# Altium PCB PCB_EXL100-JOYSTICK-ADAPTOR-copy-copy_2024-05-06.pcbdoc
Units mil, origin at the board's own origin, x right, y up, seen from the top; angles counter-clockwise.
Board outline 14061.15 x 6354.32 mil, 2 copper layers (Top Layer, Bottom Layer); 102 components, 39 nets, 293 pads, 23 vias.
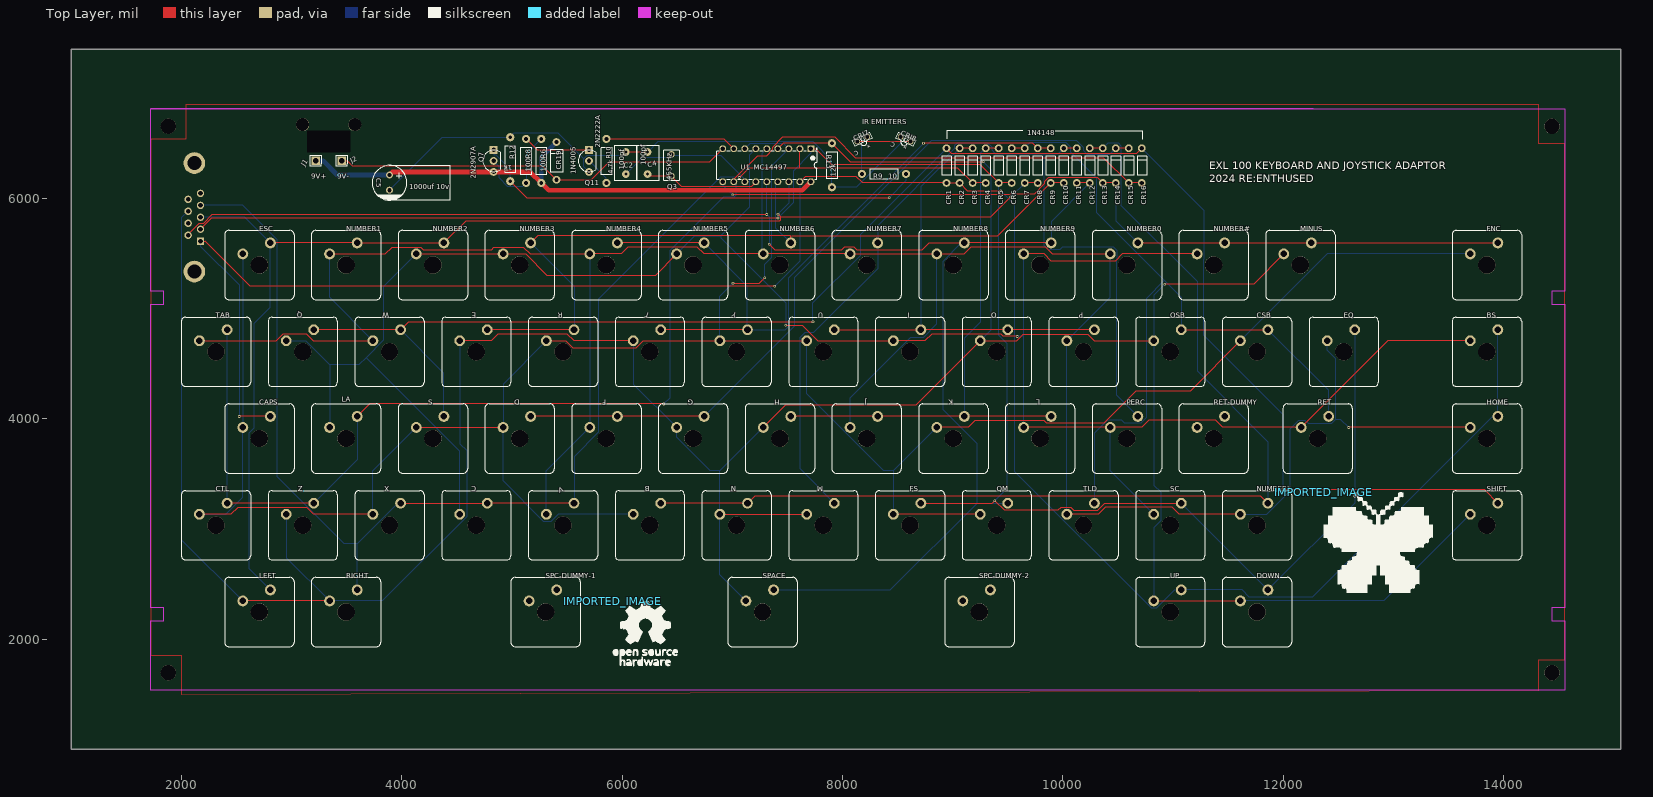
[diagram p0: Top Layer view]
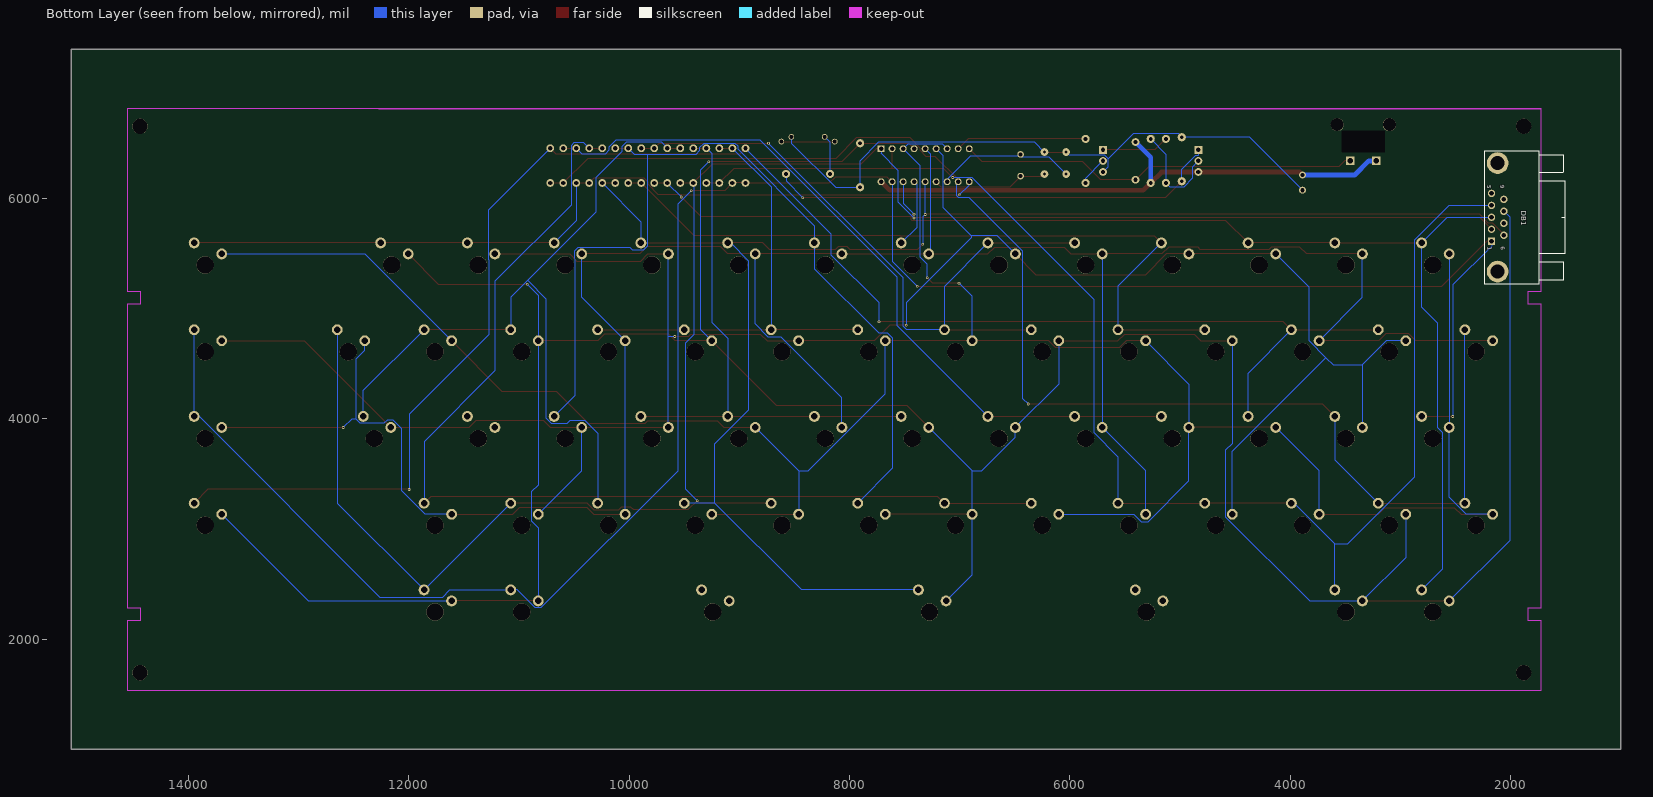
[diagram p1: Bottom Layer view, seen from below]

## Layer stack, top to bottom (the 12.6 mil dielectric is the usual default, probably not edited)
Top Layer: signal copper (thickness not stored)
Dielectric: dielectric 12.6, FR-4, Dk 4.8
Bottom Layer: signal copper (thickness not stored)

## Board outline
15061.15,1000 1000,1000 1000,7354.32 15061.15,7354.32
cut-out: 3138.86,6618.1 3532.58,6618.1 3532.56,6421.25 3138.86,6421.25

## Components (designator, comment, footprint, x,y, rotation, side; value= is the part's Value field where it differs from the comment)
B "Outemu Switch" "OUTEMU MX SWITCH FULL BOX" 6249.09,3035.43 r0 top
BS "Outemu Switch" "OUTEMU MX SWITCH FULL BOX" 13847.51,4610.23 r0 top
C "Outemu Switch" "OUTEMU MX SWITCH FULL BOX" 4674.29,3035.43 r0 top
C2 "100pf" RAD-0.2 6032.55,6322.82 r90 top
C4 "100pf" RAD-0.2 6229.4,6322.82 r90 top
C5 "1000uf 10v" CAP-D8.0-F3.5 3886.89,6145.66 r270 top
CAPS "Outemu Switch" "OUTEMU MX SWITCH FULL BOX" 2705.79,3822.83 r0 top
CR1 "1N4148" DO-35_BD2.0-L4.0-P8.00-D0.5-FD 8942.83,6299.99 r90 top
CR2 "1N4148" DO-35_BD2.0-L4.0-P8.00-D0.5-FD 9061.83,6299.99 r90 top
CR3 "1N4148" DO-35_BD2.0-L4.0-P8.00-D0.5-FD 9179.93,6299.99 r90 top
CR4 "1N4148" DO-35_BD2.0-L4.0-P8.00-D0.5-FD 9298.03,6299.99 r90 top
CR5 "1N4148" DO-35_BD2.0-L4.0-P8.00-D0.5-FD 9416.13,6299.99 r90 top
CR6 "1N4148" DO-35_BD2.0-L4.0-P8.00-D0.5-FD 9534.23,6299.99 r90 top
CR7 "1N4148" DO-35_BD2.0-L4.0-P8.00-D0.5-FD 9652.33,6299.99 r90 top
CR8 "1N4148" DO-35_BD2.0-L4.0-P8.00-D0.5-FD 9770.43,6299.99 r90 top
CR9 "1N4148" DO-35_BD2.0-L4.0-P8.00-D0.5-FD 9888.53,6299.99 r90 top
CR10 "1N4148" DO-35_BD2.0-L4.0-P8.00-D0.5-FD 10006.73,6299.99 r90 top
CR11 "1N4148" DO-35_BD2.0-L4.0-P8.00-D0.5-FD 10124.83,6299.99 r90 top
CR12 "1N4148" DO-35_BD2.0-L4.0-P8.00-D0.5-FD 10242.93,6299.99 r90 top
CR13 "1N4148" DO-35_BD2.0-L4.0-P8.00-D0.5-FD 10361.03,6299.99 r90 top
CR14 "1N4148" DO-35_BD2.0-L4.0-P8.00-D0.5-FD 10479.13,6299.99 r90 top
CR15 "1N4148" DO-35_BD2.0-L4.0-P8.00-D0.5-FD 10597.23,6299.99 r90 top
CR16 "1N4148" DO-35_BD2.0-L4.0-P8.00-D0.5-FD 10715.33,6299.99 r90 top
CR19 "1N4005" DO-41_BD2.4-L4.7-P8.70-D0.9-RD 5402.59,6342.47 r270 top
CRI7 "XC8810" LTE-302 8178.22,6539.36 r25 top
CRI8 "XC8810" LTE-302 8571.92,6539.36 r335 top
CSB "Outemu Switch" "OUTEMU MX SWITCH FULL BOX" 11760.89,4610.23 r0 top
CTL "Outemu Switch" "OUTEMU MX SWITCH FULL BOX" 2312.09,3035.43 r0 top
D "Outemu Switch" "OUTEMU MX SWITCH FULL BOX" 5067.99,3822.83 r0 top
DB1 "DB9_Male" DSUB-TH_DMR-9P 2115.24,5830.7 r0 bottom
DOWN "Outemu Switch" "OUTEMU MX SWITCH FULL BOX" 11760.89,2248.03 r0 top
E "Outemu Switch" "OUTEMU MX SWITCH FULL BOX" 4674.29,4610.23 r0 top
EQ "Outemu Switch" "OUTEMU MX SWITCH FULL BOX" 12548.29,4610.23 r0 top
ESC "Outemu Switch" "OUTEMU MX SWITCH FULL BOX" 2705.79,5397.63 r0 top
F "Outemu Switch" "OUTEMU MX SWITCH FULL BOX" 5855.39,3822.83 r0 top
FNC "Outemu Switch" "OUTEMU MX SWITCH FULL BOX" 13847.51,5397.63 r0 top
FS "Outemu Switch" "OUTEMU MX SWITCH FULL BOX" 8611.29,3035.43 r0 top
G "Outemu Switch" "OUTEMU MX SWITCH FULL BOX" 6642.79,3822.83 r0 top
H "Outemu Switch" "OUTEMU MX SWITCH FULL BOX" 7430.19,3822.83 r0 top
HOME "Outemu Switch" "OUTEMU MX SWITCH FULL BOX" 13847.51,3822.83 r0 top
I "Outemu Switch" "OUTEMU MX SWITCH FULL BOX" 8611.29,4610.23 r0 top
IMPORTED_IMAGE "IMPORTED_IMAGE" IMPORTED_IMAGE 5914.64,2346.46 r0 top
IMPORTED_IMAGE "IMPORTED_IMAGE" IMPORTED_IMAGE 12368.32,3332.87 r0 top
J "Outemu Switch" "OUTEMU MX SWITCH FULL BOX" 8217.59,3822.83 r0 top
J1 "9V+" HDR-M-2.54_1X1 3217.6,6342.51 r0 top
J2 "9V-" HDR-M-2.54_1X1 3453.82,6342.51 r0 top
K "Outemu Switch" "OUTEMU MX SWITCH FULL BOX" 9004.99,3822.83 r0 top
L "Outemu Switch" "OUTEMU MX SWITCH FULL BOX" 9792.39,3822.83 r0 top
LA "Outemu Switch" "OUTEMU MX SWITCH FULL BOX" 3493.19,3822.83 r0 top
LEFT "Outemu Switch" "OUTEMU MX SWITCH FULL BOX" 2705.79,2248.03 r0 top
M "Outemu Switch" "OUTEMU MX SWITCH FULL BOX" 7823.89,3035.43 r0 top
MINUS "Outemu Switch" "OUTEMU MX SWITCH FULL BOX" 12154.59,5397.63 r0 top
N "Outemu Switch" "OUTEMU MX SWITCH FULL BOX" 7036.49,3035.43 r0 top
NUMBER0 "Outemu Switch" "OUTEMU MX SWITCH FULL BOX" 10579.79,5397.63 r0 top
NUMBER1 "Outemu Switch" "OUTEMU MX SWITCH FULL BOX" 3493.19,5397.63 r0 top
NUMBER2 "Outemu Switch" "OUTEMU MX SWITCH FULL BOX" 4280.59,5397.63 r0 top
NUMBER3 "Outemu Switch" "OUTEMU MX SWITCH FULL BOX" 5067.99,5397.63 r0 top
NUMBER4 "Outemu Switch" "OUTEMU MX SWITCH FULL BOX" 5855.39,5397.63 r0 top
NUMBER5 "Outemu Switch" "OUTEMU MX SWITCH FULL BOX" 6642.79,5397.63 r0 top
NUMBER6 "Outemu Switch" "OUTEMU MX SWITCH FULL BOX" 7430.19,5397.63 r0 top
NUMBER7 "Outemu Switch" "OUTEMU MX SWITCH FULL BOX" 8217.59,5397.63 r0 top
NUMBER8 "Outemu Switch" "OUTEMU MX SWITCH FULL BOX" 9004.99,5397.63 r0 top
NUMBER9 "Outemu Switch" "OUTEMU MX SWITCH FULL BOX" 9792.39,5397.63 r0 top
NUMBER# "Outemu Switch" "OUTEMU MX SWITCH FULL BOX" 11367.19,5397.63 r0 top
NUMBER* "Outemu Switch" "OUTEMU MX SWITCH FULL BOX" 11760.89,3035.43 r0 top
O "Outemu Switch" "OUTEMU MX SWITCH FULL BOX" 9398.69,4610.23 r0 top
OSB "Outemu Switch" "OUTEMU MX SWITCH FULL BOX" 10973.49,4610.23 r0 top
P "Outemu Switch" "OUTEMU MX SWITCH FULL BOX" 10186.09,4610.23 r0 top
PERC "Outemu Switch" "OUTEMU MX SWITCH FULL BOX" 10579.79,3822.83 r0 top
Q "Outemu Switch" "OUTEMU MX SWITCH FULL BOX" 3099.49,4610.23 r0 top
Q3 "455KHz" FILTER-TH_2P-L7.0-W3.5-P5.00 6445.94,6303.14 r90 top
Q7 "2N2907A" TO-92-3_L4.8-W3.7-P2.54-R 4831.77,6342.51 r90 top
Q11 "2N2222A" TO-92-3_L4.8-W3.7-P2.54-R 5697.91,6342.51 r90 top
QM "Outemu Switch" "OUTEMU MX SWITCH FULL BOX" 9398.69,3035.43 r0 top
R "Outemu Switch" "OUTEMU MX SWITCH FULL BOX" 5461.69,4610.23 r0 top
R6 "100" R_AXIAL-0.4 5264.84,6342.51 r90 top
R8 "100" R_AXIAL-0.4 5127.04,6342.51 r90 top
R9 "10" R_AXIAL-0.4 8375.07,6224.4 r180 top
R10 "4.7k" R_AXIAL-0.4 5855.39,6342.51 r90 top
R12 "1k" R_AXIAL-0.4 4982.74,6357.53 r90 top
R13 "12k" R_AXIAL-0.4 7902.63,6303.14 r270 top
RET "Outemu Switch" "OUTEMU MX SWITCH FULL BOX" 12312.07,3822.83 r0 top
RET-DUMMY "K2-3.6×6.1" "OUTEMU MX SWITCH FULL BOX" 11367.19,3822.83 r0 top
RIGHT "Outemu Switch" "OUTEMU MX SWITCH FULL BOX" 3493.19,2248.03 r0 top
S "Outemu Switch" "OUTEMU MX SWITCH FULL BOX" 4280.59,3822.83 r0 top
SC "Outemu Switch" "OUTEMU MX SWITCH FULL BOX" 10973.49,3035.43 r0 top
SHIFT "Outemu Switch" "OUTEMU MX SWITCH FULL BOX" 13847.51,3035.43 r0 top
SPACE "Outemu Switch" "OUTEMU MX SWITCH FULL BOX" 7272.71,2248.03 r0 top
SPC-DUMMY-1 "K2-3.6×6.1" "OUTEMU MX SWITCH FULL BOX" 5304.21,2248.03 r0 top
SPC-DUMMY-2 "K2-3.6×6.1" "OUTEMU MX SWITCH FULL BOX" 9241.21,2248.03 r0 top
T "Outemu Switch" "OUTEMU MX SWITCH FULL BOX" 6249.09,4610.23 r0 top
TAB "Outemu Switch" "OUTEMU MX SWITCH FULL BOX" 2312.09,4610.23 r0 top
TLD "Outemu Switch" "OUTEMU MX SWITCH FULL BOX" 10186.09,3035.43 r0 top
U "Outemu Switch" "OUTEMU MX SWITCH FULL BOX" 7823.89,4610.23 r0 top
U1 "MC14497" DIP-18_L23.0-W6.5-P2.54-LS7.6-BL 7312.08,6303.14 r180 top
UP "Outemu Switch" "OUTEMU MX SWITCH FULL BOX" 10973.49,2248.03 r0 top
V "Outemu Switch" "OUTEMU MX SWITCH FULL BOX" 5461.69,3035.43 r0 top
W "Outemu Switch" "OUTEMU MX SWITCH FULL BOX" 3886.89,4610.23 r0 top
X "Outemu Switch" "OUTEMU MX SWITCH FULL BOX" 3886.89,3035.43 r0 top
Y "Outemu Switch" "OUTEMU MX SWITCH FULL BOX" 7036.49,4610.23 r0 top
Z "Outemu Switch" "OUTEMU MX SWITCH FULL BOX" 3099.49,3035.43 r0 top
? "" ? 11728.46,2818.87 r0 top

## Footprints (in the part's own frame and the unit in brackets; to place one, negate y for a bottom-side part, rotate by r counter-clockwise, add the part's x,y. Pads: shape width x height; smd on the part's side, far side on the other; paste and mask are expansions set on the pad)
CAP-D8.0-F3.5 [mm]
  round 1.6 hole 1 paste+0 mask+0.051: 1(-1.75,0) 2(1.75,0)
  silkscreen extent -3.96,-4 4.04,4
DIP-18_L23.0-W6.5-P2.54-LS7.6-BL [mm]
  rect 1.6x1.6 hole 1 paste+0 mask+0.051: 1(-10.16,-3.81)
  round 1.6 hole 1 paste+0 mask+0.051: 2(-7.62,-3.81) 3(-5.08,-3.81) 4(-2.54,-3.81) 5(0,-3.81) 6(2.54,-3.81) 7(5.08,-3.81) 8(7.62,-3.81) 9(10.16,-3.81) 10(10.16,3.81) 11(7.62,3.81) 12(5.08,3.81) 13(2.54,3.81) 14(0,3.81) 15(-2.54,3.81) 16(-5.08,3.81) 17(-7.62,3.81) 18(-10.16,3.81)
  silkscreen extent -11.58,-3.93 11.5,3.25
DO-35_BD2.0-L4.0-P8.00-D0.5-FD [mm]
  round 1.8 hole 1 paste+0 mask+0.051: 1(-4,0) 2(4,0)
  silkscreen extent -2.2,-1.1 2.2,1.1
DO-41_BD2.4-L4.7-P8.70-D0.9-RD [mm]
  round 1.8 hole 1 paste+0 mask+0.051: 1(-4.35,0) 2(4.35,0)
  silkscreen extent -2.6,-1.4 2.6,1.4
DSUB-TH_DMR-9P [mm]
  rect 1.7x1.7 hole 1.1 paste+0 mask+0.051: 1(1.42,5.52)
  round 1.7 hole 1.1 paste+0 mask+0.051: 2(1.42,2.76) 3(1.42,0) 4(1.42,-2.76) 5(1.42,-5.52) 6(-1.42,4.14) 7(-1.42,1.38) 8(-1.42,-1.38) 9(-1.42,-4.14)
  round 5 hole 3.25 paste+0 mask+0.051: 10(0,-12.5) 11(0,12.5)
  silkscreen extent -15.5,-15.4 3,15.4
FILTER-TH_2P-L7.0-W3.5-P5.00 [mil]
  round 60 hole 36 paste+0 mask+2: 1(-98.4,0) 2(98.4,0)
  silkscreen extent -138,-69 138,69
HDR-M-2.54_1X1 [mm]
  rect 2x2 hole 1.3 paste+0 mask+0.051: 1(0,0)
  silkscreen extent -1.27,-1.27 1.27,1.27
IMPORTED_IMAGE [mil]
  silkscreen extent 0,-591 590,0
LTE-302 [mil]
  round 51.5 hole 31.5 slot 31.7 at 0 deg paste+0 mask+4: A(50,0) C(-50,0)
  silkscreen extent -85,-60 85,30
"OUTEMU MX SWITCH FULL BOX" [mm]
  round 2.5 hole 1.5 paste+0 mask+0.102: 1(-3.81,2.54) 2(2.54,5.08)
  round 4 hole 4 unplated paste+0: ""(0,0)
  silkscreen extent -8,-8 8,8
R_AXIAL-0.4 [mil]
  round 74 hole 35.4 paste+0 mask+2: 1(-200,0) 2(200,0)
  silkscreen extent -124,-47 124,47
RAD-0.2 [mil]
  round 70 hole 28 paste+0 mask+2: 1(100,0) 2(-100,0)
  silkscreen extent -160,-100 160,100
TO-92-3_L4.8-W3.7-P2.54-R [mm]
  rect 1.8x1.8 hole 1 paste+0 mask+0.051: 1(2.54,0)
  round 1.8 hole 1 paste+0 mask+0.051: 2(0,0) 3(-2.54,0)
  silkscreen extent -2.48,-1.5 2.48,2.48
? [mil]

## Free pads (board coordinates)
  round 137.8 hole 137.8 unplated paste+0: ""(1879.02,1696.85) ""(1879.02,6657.47) ""(14438.05,1696.85) ""(14438.05,6657.47)
  round 118.11 hole 118.11 unplated paste+0: ""(3099.49,6671.25) ""(3571.93,6671.25)

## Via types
v1: diameter 24.02, hole 12.01, Top Layer to Bottom Layer, tented both sides, 23 vias

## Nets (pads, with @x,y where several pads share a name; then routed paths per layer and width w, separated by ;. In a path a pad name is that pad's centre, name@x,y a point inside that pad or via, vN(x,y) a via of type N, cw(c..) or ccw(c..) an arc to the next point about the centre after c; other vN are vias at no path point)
+9V: C5.1 CR19.1 J1.1 Q7.3 R6.1 U1.18 | length 5088.9
  Top Layer w43.31: C5.1 3914.01,6241.67 Q7.3@4831.77,6241.67 ; Q7.3 Q7.3@4831.77,6241.67 ; U1.18 7634.43,6075.48 5331.86,6075.48 R6.1 5165.68,6241.67 Q7.3@4831.77,6241.67
  Bottom Layer w43.31: J1.1 3286.51,6342.51 3414.47,6214.55 C5.1 ; R6.1 5264.84,6375.98 CR19.1
CONTROLGND: DB1.8 DOWN.1 E.1 G.1 H.1 LEFT.1 M.1 MINUS.1 N.1 O.1 OSB.1 R13.1 RIGHT.1 SHIFT.1 SPACE.1 T.1 U1.4 UP.1 Z.1 | length 29451.4
  Top Layer w10: LEFT.1 RIGHT.1 ; E.1 4809.45,4710.23 4870.6,4771.37 5500.55,4771.37 5561.69,4710.23 T.1 ; N.1 M.1 ; H.1 7481.14,4123.78 8662.24,4123.78 O.1 9579.31,4710.23 9639.94,4770.87 10225.44,4770.87 10286.08,4710.23 OSB.1 ; U1.4 7462.09,6503.14 R13.1 8069.64,6336.12 v1(9275.17,6336.12) ; UP.1 DOWN.1 ; v1(10922.75,5222.69) 11729.6,5222.69 MINUS.1
  Bottom Layer w10: DB1.8 2003.21,5828.91 2003.21,2900.6 LEFT.1 ; Z.1 2949.49,2741.73 RIGHT.1 3823.18,2348.03 4586.99,3111.84 4586.99,3714.57 4524.28,3777.28 E.1 ; T.1 6099.09,4316.53 G.1 6492.78,3836.46 6800.11,3529.13 6886.48,3529.13 ; SPACE.1 6886.48,2584.25 N.1 6886.48,3529.13 ; H.1 6886.48,3529.13 ; O.1 9347.91,4809.45 9347.91,6263.39 v1(9275.17,6336.12) ; UP.1 10823.49,3014.96 10886.2,3077.68 10886.2,3337.48 10823.49,3400.2 OSB.1 10823.49,5123.42 v1(10922.75,5222.69) ; DOWN.1 12910.1,2348.03 SHIFT.1
CR1_2: CR1.2 CR16.2 Q.2 S.2 SHIFT.2 W.2 | length 15037.3
  Top Layer w10: Q.2 W.2 4059.89,4883.23 v1(7730.47,4883.23) ; CR1.2 8992.65,6407.65 10665.5,6407.65 CR16.2 ; v1(11996.5,3360.38) 13822.6,3360.38 SHIFT.2
  Bottom Layer w10: W.2 4380.59,4416.53 S.2 ; v1(7730.47,4883.23) 7730.47,5054.87 8163.02,5487.43 8163.02,5677.67 CR1.2 ; CR16.2 11279.61,5893.18 11279.61,5451.71 11273.77,5445.87 11273.77,4766.67 11996.5,4043.93 v1(11996.5,3360.38)
CR2_2: CR2.2 CR3.2 I.2 O.2 P.2 U.2 | length 4272.7
  Top Layer w10: U.2 I.2 O.2 P.2 ; CR2.2 CR3.2
  Bottom Layer w10: I.2 8711.28,6106.93 CR2.2
CR4_2: CR4.2 CR5.2 H.2 J.2 K.2 L.2 | length 4994.9
  Top Layer w10: H.2 J.2 K.2 L.2 ; CR4.2 CR5.2
  Bottom Layer w10: K.2 9104.99,4731.22 9251.38,4877.61 9251.38,6410.82 CR4.2
CR7_2: CR6.2 CR7.2 CSB.2 OSB.2 RET.2 TLD.2 | length 6950
  Top Layer w10: CR6.2 CR7.2 ; OSB.2 CSB.2
  Bottom Layer w10: CR7.2 9704.84,6509.99 10027.17,6509.99 10065.78,6471.37 10065.78,6427.04 10301.99,6190.84 10301.99,5877.88 10920.9,5258.97 ; TLD.2 10286.08,3868.98 10403.61,3986.51 10534.4,3986.51 10559.75,3961.15 10705.15,3961.15 10754.68,4010.69 10754.68,5092.76 10920.9,5258.97 ; OSB.2 11073.49,5106.38 10920.9,5258.97 ; CSB.2 12412.1,4259.05 RET.2
CR9_1: CR9.1 CR10.1 E.2 NUMBER3.2 NUMBER6.2 R.2 U1.15 | length 7489.7
  Top Layer w10: E.2 R.2 ; NUMBER3.2 5233.4,5663.05 7525.02,5663.05 7530.19,5657.88 ; NUMBER6.2 7530.19,5657.88 ; CR10.1 CR9.1 9410.14,5664.12 7536.43,5664.12 7530.19,5657.88
  Bottom Layer w10: NUMBER3.2 5561.69,5203.93 R.2 ; U1.15 7389.81,6130.87 7389.81,5738 NUMBER6.2
CR9_2: CR8.2 CR9.2 NUMBER4.2 NUMBER5.2 T.2 Y.2 | length 6255.3
  Top Layer w10: NUMBER4.2 NUMBER5.2 ; T.2 Y.2 ; v1(8734.59,6503.96) 9723.93,6503.96 CR8.2 CR9.2
  Bottom Layer w10: NUMBER5.2 7136.48,5203.93 Y.2 7479.85,4810.23 7510.59,4840.97 7510.59,5279.95 v1(8734.59,6503.96)
CR10_2: CR10.2 CR11.2 M.2 NUMBER7.2 PERC.2 | length 8325.2
  Top Layer w10: CR10.2 CR11.2
  Bottom Layer w10: M.2 7608.52,3550.79 7608.52,4735.1 7654.85,4781.43 7733.44,4781.43 8317.58,5365.57 NUMBER7.2 8317.58,5755.27 9014.94,6452.63 9014.94,6478.57 9040.91,6504.53 9318.74,6504.53 9357.07,6466.2 9357.07,6438.66 9390.67,6405.05 9828.32,6405.05 ; CR10.2 9954.31,6405.05 9828.32,6405.05 ; PERC.2 10487.38,4215.24 10487.38,5450.7 10493.78,5457.11 10493.78,5526.15 10462.03,5557.9 9994.43,5557.9 9970.49,5533.95 9866.19,5533.95 9828.32,5571.83 9828.32,6405.05
CR12_2: B.2 CR12.2 CR13.2 N.2 NUMBER*.2 | length 9677.1
  Top Layer w10: B.2 N.2 7200.65,3299.59 11796.7,3299.59 NUMBER*.2 ; CR12.2 CR13.2
  Bottom Layer w10: CR13.2 10409.08,6505.53 10502.31,6505.53 10525.61,6482.22 10525.61,5940.98 11216.81,5249.79 11216.81,4438.72 11860.91,3794.64 NUMBER*.2
CR13_1: CR13.1 CR14.1 FNC.2 MINUS.2 NUMBER0.2 NUMBER#.2 U1.10 | length 7625.3
  Top Layer w10: v1(7002.01,6033.84) 9512.95,6033.84 9520.65,6041.53 9737.31,6041.53 9829.49,6133.71 9829.49,6154.42 9864.34,6189.28 10314.25,6189.28 CR13.1 CR14.1 ; NUMBER0.2 NUMBER#.2 MINUS.2 FNC.2
  Bottom Layer w10: U1.10 6912.09,6123.76 v1(7002.01,6033.84) ; CR14.1 10479.12,5798.29 NUMBER0.2
CR14_2: CR14.2 CR15.2 D.2 F.2 G.2 | length 6813.8
  Top Layer w10: D.2 F.2 G.2 ; CR14.2 CR15.2
  Bottom Layer w10: G.2 7566.8,4846.84 7566.8,5285.59 8810.47,6529.26 10118.9,6529.26 10183.89,6464.27 10183.89,6437.63 10217.16,6404.36 10426.01,6404.36 CR14.2
CR15_1: CR15.1 CR16.1 CTL.2 LA.2 TAB.2 U1.11 Z.2 | length 12561.8
  Top Layer w10: CTL.2 Z.2 ; LA.2 3706.97,4136.62 v1(6376.72,4136.62) ; U1.11 7012.09,6174.35 7223.23,6385.49 7305.99,6385.49 7362.1,6441.6 7362.1,6463.88 7453.31,6555.08 7931.82,6555.08 8119.39,6367.52 10372.22,6367.52 CR15.1 CR16.1
  Bottom Layer w10: CTL.2 TAB.2 ; Z.2 3593.18,3629.13 LA.2 ; v1(6376.72,4136.62) 6429.48,4189.39 6429.48,5526.13 6914.12,6010.77 7012.27,6010.77 7030.41,6028.92 7030.41,6134.81 U1.11
CRI7_C: CRI7.C CRI8.A | length 484.3
  Top Layer w10: CRI7.C CRI8.A
DOWN: CR5.1 CR6.1 DB1.2 DOWN.2 EQ.2 FS.2 SC.2 U1.1 | length 17207.9
  Top Layer w10: DB1.2 2273.78,5824.67 v1(7413.95,5824.67) ; U1.1 7754.56,6453.14 7894.65,6313.05 9245.58,6313.05 CR5.1 CR6.1 ; FS.2 9356.89,3235.43 v1(9380.36,3258.91) 9464.82,3174.46 9959.25,3174.46 9985.53,3200.74 10070.77,3200.74 10097.69,3173.82 10317.83,3173.82 10379.43,3235.43 SC.2
  Bottom Layer w10: v1(7413.95,5824.67) 7554.65,5965.36 7554.65,6253.22 7712.07,6410.65 U1.1 ; v1(9380.36,3258.91) 9490.27,3368.82 9490.27,4686.71 9411.74,4765.25 9411.74,6138.12 CR5.1 ; SC.2 DOWN.2 12648.31,3235.43 EQ.2
FIRE: CR11.1 CR12.1 DB1.6 NUMBER8.2 NUMBER9.2 QM.2 SPACE.2 U1.14 | length 14384.7
  Top Layer w10: DB1.6 2059.34,5675.71 2159.99,5776.37 2199.28,5776.37 2279.51,5856.59 v1(7312.09,5856.59) ; v1(7333.81,5587.51) 7384.81,5536.51 7990.6,5536.51 8017.03,5562.94 8102.27,5562.94 8130.34,5534.88 8724.18,5534.88 8786.93,5597.63 NUMBER8.2 NUMBER9.2 ; CR11.1 CR12.1
  Bottom Layer w10: U1.14 v1(7312.09,5856.59) 7333.81,5834.86 v1(7333.81,5587.51) ; SPACE.2 8433,2448.03 9220.41,3235.43 ; NUMBER8.2 9078,5597.63 8911.86,5431.5 8911.86,4084.02 9220.41,3775.48 9220.41,3235.43 ; QM.2 9220.41,3235.43 ; NUMBER9.2 9892.39,5791.97 CR12.1
GND: C2.1 C4.1 C5.2 CRI8.C Q11.3 R12.2 R13.2 | length 5685.6
  Top Layer w10: C2.1@6032.55,6422.82 C4.1
  Bottom Layer w10: C5.2 4367.66,6557.53 R12.2 5016.99,6591.79 5417.94,6591.79 5649.31,6360.42 ; Q11.3 5649.31,6291.1 5649.31,6360.42 ; C2.1@6032.55,6422.82 6002.23,6392.5 5681.4,6392.5 5649.31,6360.42 ; C4.1 6320.94,6514.37 7734.26,6514.37 7902.61,6346.01 R13.2 8125.27,6103.14 8526.6,6504.47 CRI8.C
LEFT: CR7.1 CR8.1 DB1.3 ESC.2 LEFT.2 NUMBER1.2 NUMBER2.2 U1.16 | length 11617.8
  Top Layer w10: ESC.2 NUMBER1.2 NUMBER2.2 4583.28,5800.33 7430.06,5800.33 7437.22,5807.48 7437.22,5834.06 ; v1(7413.12,5858.15) 7437.22,5834.06 ; v1(9526.78,6015.06) 9345.78,5834.06 7437.22,5834.06 ; CR7.1 CR8.1
  Bottom Layer w10: DB1.3 2572.72,5830.7 ESC.2 2805.78,5016.11 2660.18,4870.5 2660.18,3921.58 2612.66,3874.07 2612.66,2641.15 LEFT.2 ; v1(7413.12,5858.15) 7512.09,5957.11 U1.16 ; v1(9526.78,6015.06) 9652.33,6140.6 CR7.1
Q7_1: Q7.1 R9.1 R12.1 | length 4141.2
  Top Layer w10: R12.1 5131.62,6008.64 v1(8421.95,6008.64)
  Bottom Layer w10: Q7.1 4831.77,6396.09 4854.98,6396.09 4982.73,6268.33 R12.1 ; v1(8421.95,6008.64) 8575.07,6161.75 R9.1
R6_2: Q7.2 R6.2 R8.1 | length 923.2
  Bottom Layer w10: Q7.2 4883.44,6290.84 4883.44,6187.63 4961.84,6109.23 5093.77,6109.23 R8.1 5127.05,6404.72 R6.2
R8_2: Q11.1 R8.2 | length 612.3
  Top Layer w10: R8.2 5227.05,6442.51 Q11.1
R9_2: CRI7.A R9.2 | length 356.1
  Bottom Layer w10: R9.2 8175.06,6512.01 CRI7.A
R10_1: Q11.2 R10.1 | length 265.2
  Bottom Layer w10: Q11.2 5855.39,6185.03 R10.1
RIGHT: C.2 CR3.1 CR4.1 DB1.4 RIGHT.2 U1.2 V.2 X.2 | length 12680.7
  Top Layer w10: X.2 C.2 V.2 ; v1(7062.09,6191.74) 7147.91,6277.57 7612.09,6277.57 ; U1.2 7612.09,6277.57 ; CR4.1 CR3.1 9044.86,6277.57 7612.09,6277.57
  Bottom Layer w10: DB1.4 2553.93,5939.36 2868.36,5624.92 2868.36,3476.46 3476.11,2868.72 3593.18,2868.72 ; RIGHT.2 3593.18,2868.72 ; X.2 3959.89,3235.43 3593.18,2868.72 ; V.2 5561.69,3658.66 5783.3,3880.27 5783.3,5088.87 6890.11,6195.69 7058.14,6195.69 v1(7062.09,6191.74)
S$165223: 
S$165240: 
S$165247: 
S$165251: 
S$186754: 
S$186758: 
S$186762: 
U1_3: B.1 CAPS.1 CSB.1 CTL.1 D.1 ESC.1 FNC.1 FS.1 K.1 QM.1 R.1 S.1 U1.3 U1.7 U.1 X.1 Y.1 | length 22627.1
  Top Layer w10: CTL.1 2447.26,3135.43 2508.39,3196.57 3138.34,3196.57 3199.49,3135.43 X.1 ; S.1 D.1 ; R.1 5488.69,4710.23 5551.44,4647.49 6125.95,4647.49 6188.69,4710.23 Y.1 U.1 ; v1(7004.64,5232.57) 7243.38,5232.57 v1(7292.01,5281.2) ; FS.1 QM.1 ; K.1 9140.16,3922.83 9201.3,3983.97 9831.25,3983.97 9853.51,3961.7 10368.66,3961.7 10660.28,4253.33 11153.99,4253.33 CSB.1
  Bottom Layer w10: CTL.1 2400.93,3135.43 2555.78,3290.29 CAPS.1 ESC.1 ; X.1 3736.89,3529.13 S.1 ; R.1 4917.98,4316.53 D.1 4917.98,3439.19 5287.8,3069.38 5352.57,3069.38 5418.62,3135.43 B.1 ; Y.1 6886.48,5114.42 v1(7004.64,5232.57) ; U1.7 7156.78,6497.84 7467.39,6497.84 U1.3 7357.6,6298.66 7357.6,5469.41 7292.01,5403.81 v1(7292.01,5281.2) ; U.1 7673.89,4228.85 8373.6,3529.13 8461.28,3529.13 ; FS.1 8461.28,3529.13 ; K.1 8461.28,3529.13 ; CSB.1 12398.31,5497.63 FNC.1
U1_5: EQ.1 F.1 HOME.1 J.1 NUMBER0.1 NUMBER1.1 NUMBER4.1 NUMBER6.1 NUMBER7.1 NUMBER8.1 NUMBER*.1 P.1 TAB.1 TLD.1 U1.5 V.1 W.1 | length 23038.6
  Top Layer w10: TAB.1 2860.82,4710.23 2924.16,4773.58 3130.49,4773.58 3193.84,4710.23 W.1 ; NUMBER1.1 3848.57,5497.63 3909.7,5558.76 4169.45,5558.76 4191.34,5536.88 4813.01,5536.88 4835.44,5559.31 5100.66,5559.31 5162.35,5497.63 NUMBER4.1 5990.56,5497.63 6051.69,5558.77 6681.65,5558.77 6742.78,5497.63 NUMBER6.1 NUMBER7.1 NUMBER8.1 9104.99,5497.63 9168.88,5561.52 9837.4,5561.52 9901.28,5497.63 NUMBER0.1 ; TLD.1 10321.25,3135.43 10384.84,3199.02 10993.8,3199.02 11057.39,3135.43 NUMBER*.1 ; v1(12592.6,3922.83) HOME.1
  Bottom Layer w10: NUMBER1.1 3343.18,5103.93 W.1 ; V.1 5311.69,3529.13 F.1 NUMBER4.1 ; NUMBER6.1 7265.86,5511.95 7265.86,6406.92 U1.5 ; J.1 8067.59,4193.9 8616.3,4742.61 8734.76,4742.61 8854.99,4862.83 NUMBER8.1 ; TLD.1 P.1 10429.78,5103.93 NUMBER0.1 ; NUMBER*.1 11851,3135.43 12063.91,3348.36 12063.91,3912.89 12139.2,3988.19 12196.7,3988.19 12224.1,3960.79 12438.6,3960.79 12474.5,3996.68 ; EQ.1 12398.31,4625.01 12474.5,4548.79 12474.5,3996.68 ; v1(12592.6,3922.83) 12518.81,3996.68 12474.5,3996.68
U1_6: BS.1 C.1 I.1 L.1 LA.1 NUMBER2.1 NUMBER3.1 NUMBER5.1 NUMBER9.1 NUMBER#.1 PERC.1 Q.1 RET.1 SC.1 U1.6 | length 20120.7
  Top Layer w10: NUMBER2.1 NUMBER3.1 5121.86,5497.63 5312.57,5306.92 6302.07,5306.92 NUMBER5.1 ; v1(7483.62,4852.15) 7631.97,4852.15 7773.89,4710.23 I.1 8746.45,4710.23 8807.59,4771.37 9437.55,4771.37 9459.82,4749.1 v1(9585.56,4749.1) ; L.1 PERC.1 10714.95,3922.83 10778.55,3986.42 11387.5,3986.42 11451.08,3922.83 RET.1 12949.5,4710.23 BS.1 ; NUMBER9.1 9829.4,5497.63 9893.26,5433.76 10472.85,5433.76 10536.73,5497.63 NUMBER#.1
  Bottom Layer w10: Q.1 3126.51,4710.23 3343.18,4493.56 ; LA.1 3343.18,4493.56 ; NUMBER2.1 3831.78,5198.82 3831.78,4715.96 3673.8,4557.98 ; C.1 4524.28,3707.49 3673.8,4557.98 ; NUMBER5.1 6656.6,5661.45 6895.41,5661.45 ; U1.6 7154.65,6395.7 7154.65,5920.68 6895.41,5661.45 ; v1(7483.62,4852.15) 7483.62,5056.98 6895.41,5645.19 6895.41,5661.45 ; v1(9585.56,4749.1) 9642.39,4749.1 ; L.1 9642.39,4749.1 ; NUMBER9.1 9642.39,4749.1 ; PERC.1 10429.78,3529.13 SC.1 ; 3343.18,4493.56 3609.38,4493.56 3673.8,4557.98
U1_8: R10.2 U1.8 | length 1193.7
  Top Layer w10: R10.2 6922.72,6542.51 U1.8
U1_9: CR19.2 J2.1 U1.9 | length 3646
  Top Layer w10: J2.1 3504.18,6342.51 3552.88,6293.81 5279.98,6293.81 CR19.2 5717.28,6171.21 5880.28,6334.21 6793.15,6334.21 U1.9
U1_12: C2.2 Q3.2 U1.12 | length 1271
  Bottom Layer w10: C2.2@6032.55,6222.82 6186.16,6376.44 6433.4,6376.44 Q3.2@6445.94,6388.99 ; Q3.2 Q3.2@6445.94,6388.99 ; U1.12 7112.09,6174.36 6897.45,6388.99 Q3.2@6445.94,6388.99
U1_13: C4.2 Q3.1 U1.13 | length 1047.2
  Top Layer w10: C4.2 6247.48,6204.74 Q3.1 6540.64,6110.05 7168.99,6110.05 U1.13
UP: BS.2 CAPS.2 CR1.1 CR2.1 DB1.1 HOME.2 U1.17 UP.2 | length 19400.5
  Top Layer w10: DB1.1 2215.59,5613.37 2623.01,5205.96 v1(7384.49,5205.96) ; v1(2521.84,4022.83) CAPS.2 ; U1.17 7659.89,6200.94 8123.64,6200.94 8182.06,6142.51 CR1.1 CR2.1 9131.38,6072.96 v1(9434.8,6072.96)
  Bottom Layer w10: DB1.1 2171.14,5568.92 2521.84,5218.22 v1(2521.84,4022.83) ; v1(7384.49,5205.96) 7612.09,5433.55 U1.17 ; v1(9434.8,6072.96) 9559.53,5948.22 9559.53,3525.5 10799.75,2285.29 10852.51,2285.29 11015.25,2448.03 UP.2 11626.24,2448.03 11691.17,2383.1 12261.91,2383.1 13901.6,4022.83 HOME.2 BS.2
pads on no net: B. BS. C. CAPS. CSB. CTL. D. DB1.5 DB1.7 DB1.9 DB1.10 DB1.11 DOWN. E. EQ. ESC. F. FNC. FS. G. H. HOME. I. J. K. L. LA. LEFT. M. MINUS. N. NUMBER0. NUMBER1. NUMBER2. NUMBER3. NUMBER4. NUMBER5. NUMBER6. NUMBER7. NUMBER8. NUMBER9. NUMBER#. NUMBER*. O. OSB. P. PERC. Q. QM. R. RET-DUMMY. RET-DUMMY.1 RET-DUMMY.2 RET. RIGHT. S. SC. SHIFT. SPACE. SPC-DUMMY-1. SPC-DUMMY-1.1 SPC-DUMMY-1.2 SPC-DUMMY-2. SPC-DUMMY-2.1 SPC-DUMMY-2.2 T. TAB. TLD. U. UP. V. W. X. Y. Z.

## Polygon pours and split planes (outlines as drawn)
GND on Top Layer (solid): 2036.5,6854.32 2036.5,6539.36 1721.54,6539.36 1721.54,4216.53 1721.54,1854.33 1997.13,1854.33 1997.13,1500 14319.94,1539.37 14319.94,1814.96 14556.16,1814.96 14556.16,4177.16 14556.16,6499.99 14319.94,6499.99 14319.94,6854.32

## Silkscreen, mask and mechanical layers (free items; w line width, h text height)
Top Overlay:
  lines w10 net S$165223: 3886.89,5988.18 ccw(c3886.89,6145.66) 3886.89,6303.14
  lines w10 net S$165240: 3886.89,6303.14 4438.07,6303.14
  lines w10 net S$165247: 3886.89,5988.18 4438.07,5988.18
  lines w10 net S$165251: 4438.07,5988.18 4438.07,6303.14
  lines w10 net S$186754: 8945.94,6618.1 9634.91,6618.1
  lines w10 net S$186758: 8945.94,6545.3 8945.94,6618.1
  lines w10 net S$186762: 9930.2,6618.1 10717.61,6618.15 10717.61,6539.35
  text "IR EMITTERS" at 8178.22,6673.22 h47.24
  text "1N4148" at 9674.29,6574.8 h47.24
  text "C" at 8481.82,6498.15 h39.37 r155
  text "+" at 8263.69,6479.12 h39.37 r160
  text "+" at 8590.43,6447.67 h39.37 r110
  text "C" at 8130.53,6439.09 h39.37 r205
  text "EXL 100 KEYBOARD AND JOYSTICK ADAPTOR" at 11327.82,6267.71 h70.87
  text "2024 RE:ENTHUSED" at 11327.82,6149.6 h70.87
